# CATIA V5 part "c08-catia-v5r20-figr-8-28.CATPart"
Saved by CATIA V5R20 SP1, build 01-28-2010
Part number: Part1
Bounding box of the stored display mesh (mm): x 37.5 to 207.5, y 10 to 85, z 0 to 113
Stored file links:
  D:\v5_r20\psrt_files_downloaded\c08-catia-v5r20-prt\c08-catia-v5r20-figr-8-28.CATPart
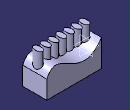
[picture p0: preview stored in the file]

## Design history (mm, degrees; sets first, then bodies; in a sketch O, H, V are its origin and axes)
Set1
  Plane1: type Offset, RefPlane xy-plane, Offset 113
Body1 (main body)
  Sketch1 on xy-plane, origin (0, 0, 0), H (1, 0, 0), V (0, 1, 0)
    line L1 (-37.5, 85) -> (37.5, 85)
    line L2 (37.5, 85) -> (37.5, -85)
    line L3 (37.5, -85) -> (-37.5, -85)
    line L4 (-37.5, -85) -> (-37.5, 85)
    axis line L5 (37.5, -85) -> (-37.5, 85)
    length L3 = 75
    length L2 = 170
    horizontal: L1 H, L3 H
    vertical: L2 V, L4 V
    midpoint: O L5
  Pad1: profile Sketch1, direction (0, 0, 1), length 83
  Sketch2 on face of Pad1, origin (37.5, 0, 0), H (0, 1, 0), V (0, 0, 1)
    spline S1 through (-85, 56.7422) (-58.5369, 80.0687) (-27.7952, 70.201) (85, 83)
    reference projected line E1 (85, 0) -> (85, 83) from edge [face of Pad1 | face of Pad1]
    reference projected line E2 (-85, 0) -> (-85, 83) from edge [face of Pad1 | face of Pad1]
    reference projected line E3 (-85, 83) -> (85, 83) from edge [face of Pad1 | face of Pad1]
    point P1 (85, 83)
    point P3 (-85, 56.7422)
    coincidence: P1 E1, P3 E2, P1 E3
  Pocket1: profile Sketch2, direction (-1, 0, 0), length 83
  Rotate1: ToTransfor Pocket1, Axis edge [face of Pad1 | face of Pad1], Angle 90
  Sketch3 on Plane1, origin (0, 0, 113), H (1, 0, 0), V (0, 1, 0)
    ellipse A1 centre (195.4286, 45.9861) semi-axes 14.9247, 8.8005 rotation 90
  Pad2: profile Sketch3, direction (0, 0, -1), up to face of Pocket1
  RectPattern1: of Pad2, direction 1 instances 7, spacing 24, along edge [face of Pad1 | face of Pad1]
